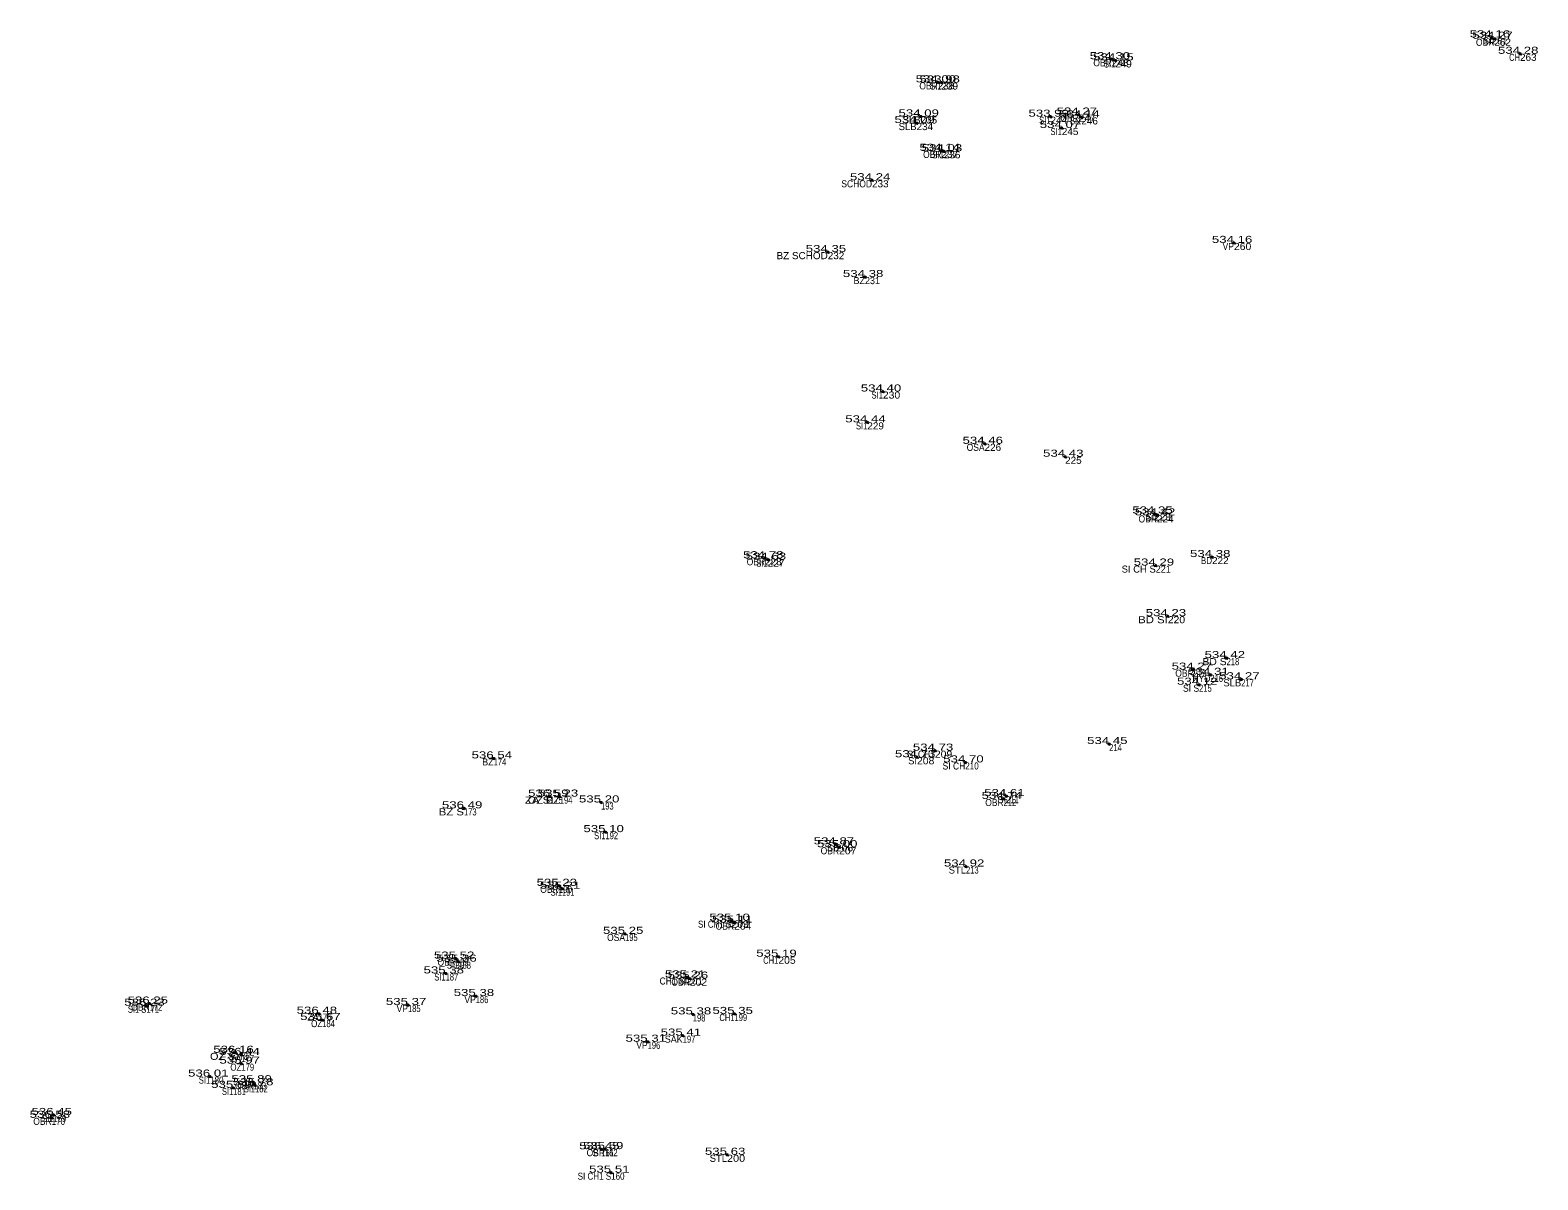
# Model space of a CAD drawing. Extents: x -643086 to -639283, y -1131805 to -1123269.
# Drawn here: x -642966.2 to -642902.1, y -1131349.2 to -1131300.4 of the extents above; entities that cross this region are included whole.
import ezdxf
from ezdxf.enums import TextEntityAlignment as Align

# ---------------------------------------------------------------- set-up
doc = ezdxf.new("R2010")
doc.units = 0
doc.header["$LTSCALE"] = 0.12
doc.header["$PDMODE"] = 32
doc.header["$PDSIZE"] = 0.06
for name, color, linetype in [('1', 7, 'Continuous'), ('2', 7, 'Continuous'), ('3', 7, 'Continuous'), ('4', 7, 'Continuous')]:
    doc.layers.add(name, color=color, linetype=linetype)

msp = doc.modelspace()

# ---------------------------------------------------------------- linework, layer by layer
at = {"layer": '1'}
for p in [(-642904.09, -1131300.71), (-642903.98, -1131300.77), (-642902.89, -1131301.41), (-642920.23, -1131301.64), (-642920.08, -1131301.69), (-642927.62, -1131302.62), (-642927.46, -1131302.63), (-642928.35, -1131304.07), (-642922.83, -1131304.08), (-642921.63, -1131303.99), (-642921.52, -1131304.11), (-642928.52, -1131304.35), (-642922.35, -1131304.56), (-642927.46, -1131305.53), (-642927.36, -1131305.55), (-642930.41, -1131306.78), (-642932.29, -1131309.83), (-642915.04, -1131309.44), (-642930.71, -1131310.89), (-642929.95, -1131315.75), (-642930.61, -1131317.06), (-642925.63, -1131317.97), (-642922.21, -1131318.52), (-642918.42, -1131320.93), (-642918.31, -1131321.01), (-642934.95, -1131322.83), (-642934.84, -1131322.89), (-642918.36, -1131323.14), (-642915.97, -1131322.78), (-642917.85, -1131325.29), (-642915.35, -1131327.07), (-642916.75, -1131327.56), (-642916.04, -1131327.78), (-642916.52, -1131328.2), (-642914.73, -1131327.97), (-642927.74, -1131331), (-642920.34, -1131330.72), (-642946.48, -1131331.33), (-642928.5, -1131331.28), (-642926.45, -1131331.5), (-642944.08, -1131332.95), (-642943.67, -1131332.95), (-642924.71, -1131332.93), (-642947.74, -1131333.45), (-642941.92, -1131333.2), (-642924.82, -1131333.05), (-642941.73, -1131334.46), (-642931.95, -1131334.98), (-642931.81, -1131335.1), (-642926.42, -1131335.92), (-642943.72, -1131336.74), (-642943.58, -1131336.86), (-642936.38, -1131338.22), (-642936.27, -1131338.3), (-642940.9, -1131338.78), (-642948.08, -1131339.83), (-642947.98, -1131339.96), (-642934.39, -1131339.75), (-642948.52, -1131340.46), (-642938.27, -1131340.63), (-642938.15, -1131340.68), (-642961.23, -1131341.83), (-642961.09, -1131341.74), (-642950.12, -1131341.8), (-642947.24, -1131341.42), (-642953.91, -1131342.17), (-642953.76, -1131342.44), (-642938.02, -1131342.2), (-642936.25, -1131342.18), (-642938.45, -1131343.1), (-642957.45, -1131343.83), (-642939.94, -1131343.36), (-642957.19, -1131343.92), (-642957.19, -1131344.29), (-642958.52, -1131344.84), (-642956.68, -1131345.08), (-642957.54, -1131345.32), (-642956.61, -1131345.21), (-642965.25, -1131346.59), (-642965.17, -1131346.47), (-642941.91, -1131347.93), (-642941.75, -1131347.92), (-642936.57, -1131348.16), (-642941.49, -1131348.92)]:
    msp.add_point(p, dxfattribs=at)

# ---------------------------------------------------------------- texts
at = {"layer": '2'}
for s, p in [('261', (-642904.09, -1131301.01)), ('201', (-642938.27, -1131340.93))]:
    msp.add_text(s, height=0.3, dxfattribs=at).set_placement(p)
for s, width, p in [('262', 1.05, (-642903.98, -1131301.07)), ('263', 1.05, (-642902.89, -1131301.71)), ('248', 1.05, (-642920.23, -1131301.94)), ('249', 1.05, (-642920.08, -1131301.99)), ('238', 1.05, (-642927.62, -1131302.92)), ('239', 1.05, (-642927.46, -1131302.93)), ('235', 1.05, (-642928.35, -1131304.37)), ('244', 1.05, (-642922.83, -1131304.38)), ('247', 1.05, (-642921.63, -1131304.29)), ('246', 1.05, (-642921.52, -1131304.41)), ('234', 1.05, (-642928.52, -1131304.65)), ('245', 1.05, (-642922.35, -1131304.86)), ('237', 1.05, (-642927.46, -1131305.83)), ('236', 1.05, (-642927.36, -1131305.85)), ('233', 1.05, (-642930.41, -1131307.08)), ('232', 1.05, (-642932.29, -1131310.13)), ('260', 1.1, (-642915.04, -1131309.74)), ('231', 0.95, (-642930.71, -1131311.19)), ('230', 1.1, (-642929.95, -1131316.05)), ('229', 1.05, (-642930.61, -1131317.36)), ('226', 1.05, (-642925.63, -1131318.27)), ('225', 1.05, (-642922.21, -1131318.82)), ('223', 1.05, (-642918.42, -1131321.23)), ('224', 1.05, (-642918.31, -1131321.31)), ('228', 1.05, (-642934.95, -1131323.13)), ('227', 1.05, (-642934.84, -1131323.19)), ('221', 0.95, (-642918.36, -1131323.44)), ('222', 1.05, (-642915.97, -1131323.08)), ('220', 1.1, (-642917.85, -1131325.59)), ('218', 0.8, (-642915.35, -1131327.37)), ('219', 0.8, (-642916.75, -1131327.86)), ('216', 0.8, (-642916.04, -1131328.08)), ('215', 0.8, (-642916.52, -1131328.5)), ('217', 0.8, (-642914.73, -1131328.27)), ('209', 1.1, (-642927.74, -1131331.3)), ('214', 0.8, (-642920.34, -1131331.02)), ('174', 0.8, (-642946.48, -1131331.63)), ('208', 1.1, (-642928.5, -1131331.58)), ('210', 0.85, (-642926.45, -1131331.8)), ('175', 0.8, (-642944.08, -1131333.25)), ('194', 0.8, (-642943.67, -1131333.25)), ('211', 0.7, (-642924.71, -1131333.23)), ('173', 0.8, (-642947.74, -1131333.75)), ('193', 0.8, (-642941.92, -1131333.5)), ('212', 0.8, (-642924.82, -1131333.35)), ('192', 0.8, (-642941.73, -1131334.76)), ('206', 1.1, (-642931.95, -1131335.28)), ('207', 1.1, (-642931.81, -1131335.4)), ('213', 0.8, (-642926.42, -1131336.22)), ('190', 0.85, (-642943.72, -1131337.04)), ('191', 0.7, (-642943.58, -1131337.16)), ('203', 1.1, (-642936.38, -1131338.52)), ('204', 1.1, (-642936.27, -1131338.6)), ('195', 0.8, (-642940.9, -1131339.08)), ('189', 0.8, (-642948.08, -1131340.13)), ('188', 0.8, (-642947.98, -1131340.26)), ('205', 1.1, (-642934.39, -1131340.05)), ('187', 0.8, (-642948.52, -1131340.76)), ('202', 1.1, (-642938.15, -1131340.98)), ('171', 0.7, (-642961.23, -1131342.13)), ('172', 0.8, (-642961.09, -1131342.04)), ('185', 0.8, (-642950.12, -1131342.1)), ('186', 0.8, (-642947.24, -1131341.72)), ('176', 0.8, (-642953.91, -1131342.47)), ('184', 0.8, (-642953.76, -1131342.74)), ('198', 0.8, (-642938.02, -1131342.5)), ('199', 0.8, (-642936.25, -1131342.48)), ('197', 0.8, (-642938.45, -1131343.4)), ('178', 0.8, (-642957.45, -1131344.13)), ('196', 0.8, (-642939.94, -1131343.66)), ('177', 0.8, (-642957.19, -1131344.22)), ('179', 0.8, (-642957.19, -1131344.59)), ('180', 0.85, (-642958.52, -1131345.14)), ('183', 0.8, (-642956.68, -1131345.38)), ('181', 0.7, (-642957.54, -1131345.62)), ('182', 0.8, (-642956.61, -1131345.51)), ('170', 0.85, (-642965.25, -1131346.89)), ('169', 0.8, (-642965.17, -1131346.77)), ('161', 0.7, (-642941.91, -1131348.23)), ('162', 0.8, (-642941.75, -1131348.22)), ('200', 1.15, (-642936.57, -1131348.46)), ('160', 0.85, (-642941.49, -1131349.22))]:
    msp.add_text(s, height=0.3, dxfattribs=dict(at, width=width)).set_placement(p)
at = {"layer": '3', "width": 1.4}
for s, p in [('534 16 ', (-642904.09, -1131300.71)), ('534 27 ', (-642903.98, -1131300.77)), ('534 30 ', (-642920.23, -1131301.64)), ('534 15 ', (-642920.08, -1131301.69)), ('534 28 ', (-642902.89, -1131301.41)), ('534 00 ', (-642927.62, -1131302.62)), ('533 98 ', (-642927.46, -1131302.63)), ('534 09 ', (-642928.52, -1131304.35)), ('534 09 ', (-642928.35, -1131304.07)), ('533 99 ', (-642922.83, -1131304.08)), ('534 27 ', (-642921.63, -1131303.99)), ('534 14 ', (-642921.52, -1131304.11)), ('534 07 ', (-642922.35, -1131304.56)), ('534 14 ', (-642927.46, -1131305.53)), ('534 03 ', (-642927.36, -1131305.55)), ('534 24 ', (-642930.41, -1131306.78)), ('534 16 ', (-642915.04, -1131309.44)), ('534 35 ', (-642932.29, -1131309.83)), ('534 38 ', (-642930.71, -1131310.89)), ('534 40 ', (-642929.95, -1131315.75)), ('534 44 ', (-642930.61, -1131317.06)), ('534 46 ', (-642925.63, -1131317.97)), ('534 43 ', (-642922.21, -1131318.52)), ('534 35 ', (-642918.42, -1131320.93)), ('534 42 ', (-642918.31, -1131321.01)), ('534 78 ', (-642934.95, -1131322.83)), ('534 63 ', (-642934.84, -1131322.89)), ('534 38 ', (-642915.97, -1131322.78)), ('534 29 ', (-642918.36, -1131323.14)), ('534 23 ', (-642917.85, -1131325.29)), ('534 42 ', (-642915.35, -1131327.07)), ('534 27 ', (-642916.75, -1131327.56)), ('534 31 ', (-642916.04, -1131327.78)), ('534 27 ', (-642914.73, -1131327.97)), ('534 12 ', (-642916.52, -1131328.2)), ('534 45 ', (-642920.34, -1131330.72)), ('536 54 ', (-642946.48, -1131331.33)), ('534 73 ', (-642928.5, -1131331.28)), ('534 73 ', (-642927.74, -1131331)), ('534 70 ', (-642926.45, -1131331.5)), ('536 59 ', (-642944.08, -1131332.95)), ('535 23 ', (-642943.67, -1131332.95)), ('535 20 ', (-642941.92, -1131333.2)), ('534 74 ', (-642924.82, -1131333.05)), ('534 61 ', (-642924.71, -1131332.93)), ('536 49 ', (-642947.74, -1131333.45)), ('535 10 ', (-642941.73, -1131334.46)), ('534 87 ', (-642931.95, -1131334.98)), ('535 00 ', (-642931.81, -1131335.1)), ('534 92 ', (-642926.42, -1131335.92)), ('535 23 ', (-642943.72, -1131336.74)), ('535 21 ', (-642943.58, -1131336.86)), ('535 10 ', (-642936.38, -1131338.22)), ('535 11 ', (-642936.27, -1131338.3)), ('535 25 ', (-642940.9, -1131338.78)), ('535 52 ', (-642948.08, -1131339.83)), ('535 36 ', (-642947.98, -1131339.96)), ('535 19 ', (-642934.39, -1131339.75)), ('535 38 ', (-642948.52, -1131340.46)), ('535 21 ', (-642938.27, -1131340.63)), ('535 26 ', (-642938.15, -1131340.68)), ('535 38 ', (-642947.24, -1131341.42)), ('536 23 ', (-642961.23, -1131341.83)), ('536 25 ', (-642961.09, -1131341.74)), ('536 48 ', (-642953.91, -1131342.17)), ('535 37 ', (-642950.12, -1131341.8)), ('535 38 ', (-642938.02, -1131342.2)), ('535 35 ', (-642936.25, -1131342.18)), ('535 67 ', (-642953.76, -1131342.44)), ('535 31 ', (-642939.94, -1131343.36)), ('535 41 ', (-642938.45, -1131343.1)), ('536 16 ', (-642957.45, -1131343.83)), ('536 44 ', (-642957.19, -1131343.92)), ('535 97 ', (-642957.19, -1131344.29)), ('536 01 ', (-642958.52, -1131344.84)), ('535 89 ', (-642957.54, -1131345.32)), ('535 89 ', (-642956.68, -1131345.08)), ('535 78 ', (-642956.61, -1131345.21)), ('536 58 ', (-642965.25, -1131346.59)), ('536 45 ', (-642965.17, -1131346.47)), ('535 45 ', (-642941.91, -1131347.93)), ('535 59 ', (-642941.75, -1131347.92)), ('535 63 ', (-642936.57, -1131348.16)), ('535 51 ', (-642941.49, -1131348.92))]:
    msp.add_text(s, height=0.3, dxfattribs=at).set_placement(p, align=Align.CENTER)
at = {"layer": '4'}
for s, width, p in [('OBR', 0.9, (-642903.98, -1131301.07)), ('CH', 0.8, (-642902.89, -1131301.71)), ('OBR', 0.9, (-642920.23, -1131301.94)), ('SI1', 0.8, (-642920.08, -1131301.99)), ('OBR', 0.9, (-642927.62, -1131302.92)), ('SI1', 0.8, (-642927.46, -1131302.93)), ('SI1', 0.8, (-642922.83, -1131304.38)), ('OBR', 0.9, (-642921.63, -1131304.29)), ('SI1', 0.8, (-642921.52, -1131304.41)), ('SI1', 0.8, (-642922.35, -1131304.86)), ('OBR', 0.9, (-642927.46, -1131305.83)), ('SI1', 0.8, (-642927.36, -1131305.85)), ('SCHOD', 0.9, (-642930.41, -1131307.08)), ('BZ SCHOD', 1.05, (-642932.29, -1131310.13)), ('VP', 0.9, (-642915.04, -1131309.74)), ('BZ', 0.95, (-642930.71, -1131311.19)), ('SI1', 0.8, (-642929.95, -1131316.05)), ('SI1', 0.8, (-642930.61, -1131317.36)), ('OSA', 0.9, (-642925.63, -1131318.27)), ('OBR', 0.9, (-642918.31, -1131321.31)), ('OBR', 0.9, (-642934.95, -1131323.13)), ('SI1', 0.8, (-642934.84, -1131323.19)), ('BD', 0.85, (-642915.97, -1131323.08)), ('BD SI', 1.2, (-642917.85, -1131325.59)), ('BD S', 1.1, (-642915.35, -1131327.37)), ('OBR', 0.9, (-642916.75, -1131327.86)), ('HYD', 0.9, (-642916.04, -1131328.08)), ('SI S', 0.9, (-642916.52, -1131328.5)), ('SI CH1', 0.9, (-642927.74, -1131331.3)), ('BZ', 0.95, (-642946.48, -1131331.63)), ('SI CH', 0.9, (-642926.45, -1131331.8)), ('ZA S', 1.2, (-642944.08, -1131333.25)), ('OZ BZ', 1.15, (-642943.67, -1131333.25)), ('BZ S', 1.2, (-642947.74, -1131333.75)), ('OBR', 0.9, (-642924.82, -1131333.35)), ('SI1', 0.8, (-642941.73, -1131334.76)), ('OBR', 0.9, (-642931.81, -1131335.4)), ('OBR', 0.9, (-642943.72, -1131337.04)), ('SI1', 0.8, (-642943.58, -1131337.16)), ('SI CH1 S', 0.85, (-642936.38, -1131338.52)), ('OBR', 0.9, (-642936.27, -1131338.6)), ('OSA', 0.9, (-642940.9, -1131339.08)), ('OBR', 0.9, (-642948.08, -1131340.13)), ('SI1', 0.8, (-642947.98, -1131340.26)), ('CH1', 0.8, (-642934.39, -1131340.05)), ('SI1', 0.8, (-642948.52, -1131340.76)), ('CH1 SI', 0.9, (-642938.27, -1131340.93)), ('OBR', 0.9, (-642938.15, -1131340.98)), ('SI1 S', 0.8, (-642961.23, -1131342.13)), ('OBR', 0.9, (-642961.09, -1131342.04)), ('VP', 0.9, (-642950.12, -1131342.1)), ('VP', 0.9, (-642947.24, -1131341.72)), ('ZA', 0.95, (-642953.91, -1131342.47)), ('OZ', 0.85, (-642953.76, -1131342.74)), ('CH1', 0.8, (-642936.25, -1131342.48)), ('SAK', 0.95, (-642938.45, -1131343.4)), ('OZ S', 1.15, (-642957.45, -1131344.13)), ('VP', 0.9, (-642939.94, -1131343.66)), ('ZA', 0.95, (-642957.19, -1131344.22)), ('OZ', 0.85, (-642957.19, -1131344.59)), ('SI1', 0.8, (-642958.52, -1131345.14)), ('OBR', 0.9, (-642956.68, -1131345.38)), ('SI1', 0.8, (-642957.54, -1131345.62)), ('SI1', 0.8, (-642956.61, -1131345.51)), ('OBR', 0.9, (-642965.25, -1131346.89)), ('SI1', 0.8, (-642965.17, -1131346.77)), ('OBR', 0.9, (-642941.75, -1131348.22)), ('SI CH1 S', 0.85, (-642941.49, -1131349.22))]:
    msp.add_text(s, height=0.3, dxfattribs=dict(at, width=width)).set_placement(p, align=Align.RIGHT)
for s, p in [('SI', (-642904.09, -1131301.01)), ('SLB', (-642928.35, -1131304.37)), ('SLB', (-642928.52, -1131304.65)), ('SI', (-642918.42, -1131321.23)), ('SI CH S', (-642918.36, -1131323.44)), ('SLB', (-642914.73, -1131328.27)), ('SI', (-642928.5, -1131331.58)), ('SI', (-642924.71, -1131333.23)), ('SI', (-642931.95, -1131335.28)), ('STL', (-642926.42, -1131336.22)), ('SI', (-642941.91, -1131348.23)), ('STL', (-642936.57, -1131348.46))]:
    msp.add_text(s, height=0.3, dxfattribs=at).set_placement(p, align=Align.RIGHT)

doc.saveas('drawing.dxf')
